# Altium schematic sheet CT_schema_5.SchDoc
size 357 x 184 mm
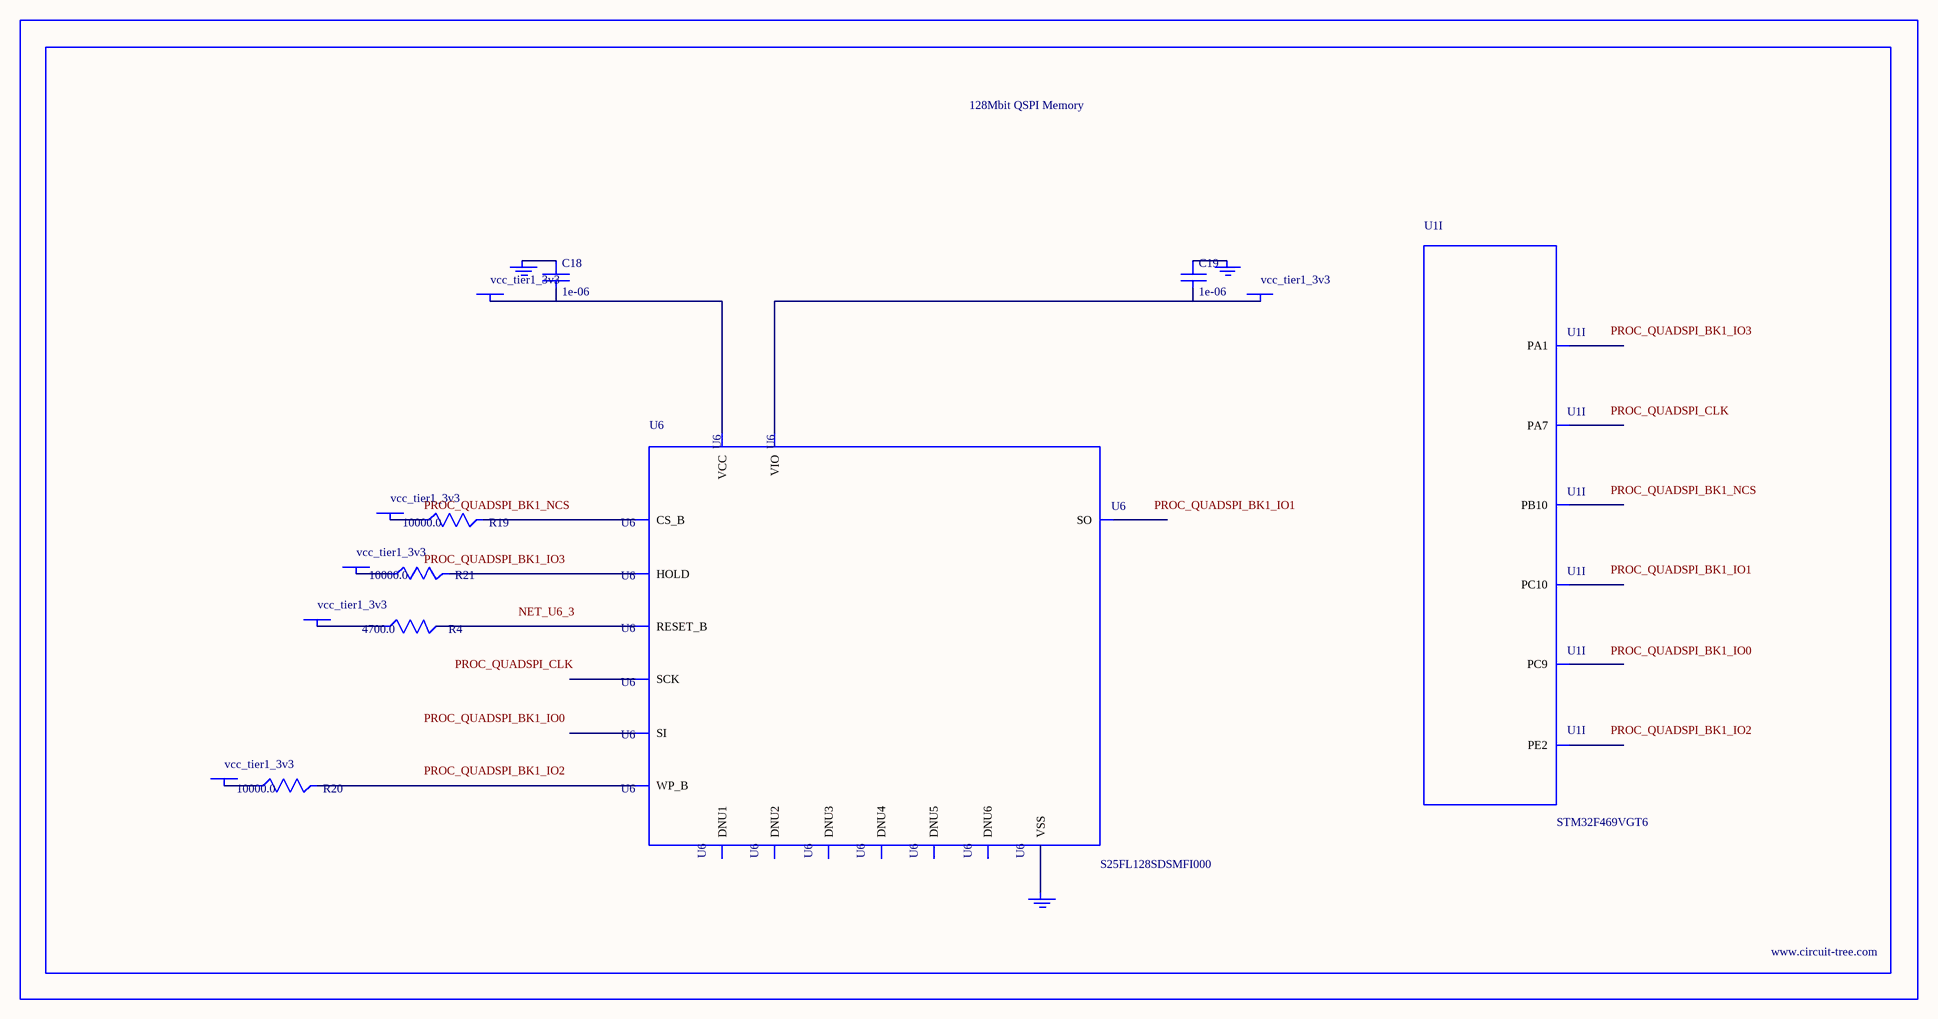
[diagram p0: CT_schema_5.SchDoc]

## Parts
BORDER4  (no value)
C18  1e-06  [C0603]
C19  1e-06  [C0603]
GND_INSTANCE_4_0  (no value)
GND_INSTANCE_4_1  (no value)
GND_INSTANCE_4_2  (no value)
POWER_INSTANCE_4_0  vcc_tier1_3v3
POWER_INSTANCE_4_1  vcc_tier1_3v3
POWER_INSTANCE_4_2  vcc_tier1_3v3
POWER_INSTANCE_4_3  vcc_tier1_3v3
POWER_INSTANCE_4_4  vcc_tier1_3v3
POWER_INSTANCE_4_5  vcc_tier1_3v3
R4  4700.0  [R0603]
R19  10000.0  [R0603]
R20  10000.0  [R0603]
R21  10000.0  [R0603]
U1  STM32F469VGT6  [LQFP100]  (part I of 10)
U6  S25FL128SDSMFI000  [S25FL128SDSMFI000]

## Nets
NetC18_1: C18.1 GND_INSTANCE_4_0.0(GND)
NetC18_2: C18.2 POWER_INSTANCE_4_1.0(PWR) U6.2(VCC)
NetC19_1: C19.1 GND_INSTANCE_4_1.0(GND)
NetC19_2: C19.2 POWER_INSTANCE_4_4.0(PWR) U6.14(VIO)
NetGND_INSTANCE_4_2_0: GND_INSTANCE_4_2.0(GND) U6.10(VSS)
NetPOWER_INSTANCE_4_0_0: POWER_INSTANCE_4_0.0(PWR) R21.1
NetPOWER_INSTANCE_4_2_0: POWER_INSTANCE_4_2.0(PWR) R19.1
NetPOWER_INSTANCE_4_3_0: POWER_INSTANCE_4_3.0(PWR) R20.1
NetPOWER_INSTANCE_4_5_0: POWER_INSTANCE_4_5.0(PWR) R4.1
NetR4_2: R4.2 U6.3(RESET_B)
NetR19_2: R19.2 U6.7(CS_B)
NetR20_2: R20.2 U6.9(WP_B)
NetR21_2: R21.2 U6.1(HOLD)

Not connected (* = marked no-connect by the designer): U1 1(PE2) 20(PA1) 28(PA7) 41(PB10) 69(PC9) 81(PC10); U6 4(DNU1) 5(DNU2) 6(DNU6) 8(SO) 11(DNU3) 12(DNU4) 13(DNU5) 15(SI) 16(SCK)

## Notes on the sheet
- Labels drawn without touching a wire or pin: NET_U6_3, PROC_QUADSPI_BK1_IO0, PROC_QUADSPI_BK1_IO1, PROC_QUADSPI_BK1_IO2, PROC_QUADSPI_BK1_IO3, PROC_QUADSPI_BK1_NCS, PROC_QUADSPI_CLK

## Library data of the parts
BORDER4 = BORDER_PAGE4
C18 C19 = C0603C105K3RACTU
GND_INSTANCE_4_0-GND_INSTANCE_4_2 = GND
POWER_INSTANCE_4_0-POWER_INSTANCE_4_5 = PWR
R4 = RC0603JR-074K7L
R19-R21 = RC0603JR-0710KL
